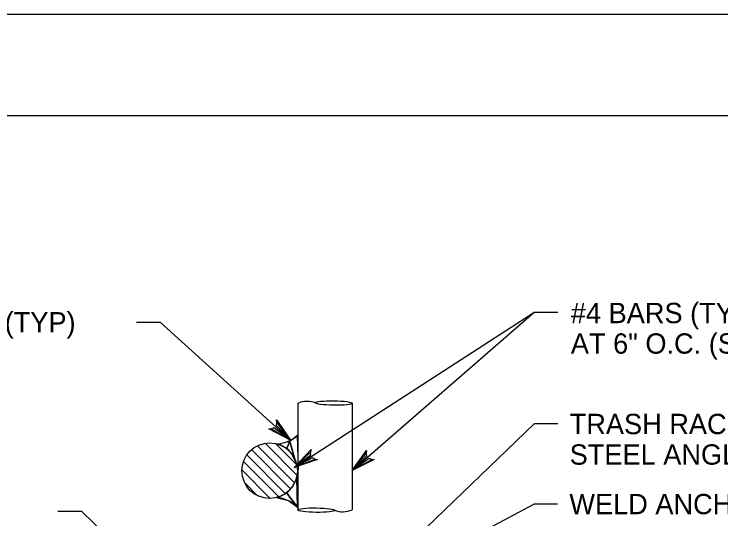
# Model space of a CAD drawing. Extents: x 636462 to 639890, y 299944 to 300538.
# Drawn here: x 639428.9 to 639533.2, y 300464 to 300538.4 of the extents above; entities that cross this region are included whole.
import ezdxf

# ---------------------------------------------------------------- set-up
doc = ezdxf.new("R2010")
doc.units = 0
for name, color, linetype in [('1', 7, 'Continuous'), ('Default', 7, 'Continuous'), ('PLT-BNDY', 7, 'Continuous')]:
    doc.layers.add(name, color=color, linetype=linetype)

msp = doc.modelspace()

# ---------------------------------------------------------------- linework, layer by layer
at = {"layer": '1'}
msp.add_lwpolyline([(639810.91, 299959.45), (639810.91, 300523.45), (639024.91, 300523.45), (639024.91, 299959.45), (639810.91, 299959.45), (639810.91, 299985.81), (639610.91, 299985.81), (639610.91, 300050.49), (639810.91, 300050.49), (639810.91, 300079.45), (639610.91, 300079.45), (639610.91, 299959.45), (639689.72, 299959.45), (639689.72, 299985.81), (639689.72, 299959.45), (639766.72, 299959.45), (639766.72, 299985.81), (639766.72, 299973.49), (639810.91, 299973.49)], dxfattribs=at)
at = {"layer": 'Default'}
for p, q in [((639470.23, 300471.6), (639505.61, 300494.46)), ((639478.78, 300471.16), (639505.61, 300494.46)), ((639509.11, 300494.46), (639505.61, 300494.46)), ((639446.95, 300493), (639450.45, 300493)), ((639469.66, 300475.61), (639450.45, 300493)), ((639470.75, 300481.05), (639470.75, 300465.34)), ((639478.78, 300481.05), (639478.78, 300465.34)), ((639483.19, 300456.49), (639505.64, 300478)), ((639509.13, 300478), (639505.64, 300478)), ((639470.28, 300469.33), (639464.81, 300474.79)), ((639470.63, 300470.45), (639465.93, 300475.15)), ((639470.59, 300471.96), (639467.44, 300475.11)), ((639468.91, 300467.75), (639463.23, 300473.43)), ((639469.69, 300468.44), (639463.92, 300474.22)), ((639467.94, 300467.25), (639462.73, 300472.46)), ((639466.69, 300467.02), (639462.5, 300471.22)), ((639464.82, 300467.42), (639462.91, 300469.34)), ((639487.37, 300456.49), (639505.58, 300466.19)), ((639509.08, 300466.19), (639505.58, 300466.19)), ((639435.32, 300465.12), (639438.82, 300465.12)), ((639469.85, 300435.43), (639438.82, 300465.12))]:
    msp.add_line(p, q, dxfattribs=at)
for points in [[(639467.68, 300478.25), (639467.63, 300478.59), (639469.66, 300475.61), (639467.68, 300478.25), (639467.58, 300477.84), (639469.66, 300475.61), (639467.23, 300477.44), (639466.85, 300477.29), (639469.66, 300475.61), (639466.47, 300477.29), (639466.85, 300477.29)], [(639473.31, 300472.79), (639473.66, 300472.74), (639470.23, 300471.6), (639473.31, 300472.79), (639472.94, 300473), (639470.23, 300471.6), (639472.66, 300473.44), (639472.61, 300473.85), (639470.23, 300471.6), (639472.72, 300474.22), (639472.61, 300473.85)], [(639481.68, 300472.74), (639482.02, 300472.74), (639478.78, 300471.16), (639481.68, 300472.74), (639481.29, 300472.9), (639478.78, 300471.16), (639480.95, 300473.3), (639480.85, 300473.71), (639478.78, 300471.16), (639480.9, 300474.08), (639480.85, 300473.71)]]:
    msp.add_lwpolyline(points, dxfattribs=at)
for points in [[(639469.57, 300475.42), (639470.43, 300472.48), (639470.84, 300471.33), (639470.72, 300476.28)], [(639469.11, 300474.44), (639469.57, 300475.42), (639468.01, 300475.02)], [(639470.43, 300472.48), (639469.57, 300475.42), (639469.11, 300474.44), (639469.8, 300473.58)], [(639469.11, 300467.82), (639470.72, 300465.75), (639470.6, 300470.06), (639469.97, 300468.74)], [(639470.72, 300465.75), (639469.11, 300467.82), (639467.73, 300467.13), (639469.4, 300466.73)]]:
    msp.add_lwpolyline(points, close=True, dxfattribs=at)
msp.add_circle((639466.59, 300471.11), 4.1, dxfattribs=at)
for centre, radius, start, end in [((639472.15, 300477.78), 3.55, 69.2636, 113.1646), ((639467.38, 300480.03), 4.97, 273.9882, 313.2132), ((639467.2, 300462.2), 4.97, 46.7868, 84.4707), ((639477.39, 300468.6), 3.55, 249.2636, 293.1646)]:
    msp.add_arc(centre, radius, start, end, dxfattribs=at)
for centre, major_axis in [((639476.05, 300481.09), (-2.73, 0.04)), ((639473.48, 300465.29), (2.73, -0.04))]:
    msp.add_ellipse(centre, major_axis=major_axis, ratio=0.121225, start_param=0, end_param=6.283175, dxfattribs=at)
at = {"layer": 'PLT-BNDY'}
msp.add_lwpolyline([(638984.91, 300538.45), (639825.91, 300538.45), (639825.91, 299944.45), (638984.91, 299944.45)], close=True, dxfattribs=at)

# ---------------------------------------------------------------- texts
at = {"layer": 'Default'}
for s, p in [('#4 BARS (TYP) PLACED', (639511.05, 300492.87)), ('WELD BARS (TYP)', (639402.76, 300491.5)), ('AT 6" O.C. (SEE DETAIL)', (639511.05, 300488.37)), ('TRASH RACK FRAME 2" x 2" x 1/8"', (639510.88, 300476.5)), ('STEEL ANGLE (TYP)', (639510.88, 300472)), ('WELD ANCHOR BOLT ANGLE', (639510.83, 300464.69))]:
    msp.add_text(s, height=2.998, dxfattribs=at).set_placement(p)

doc.saveas('drawing.dxf')
